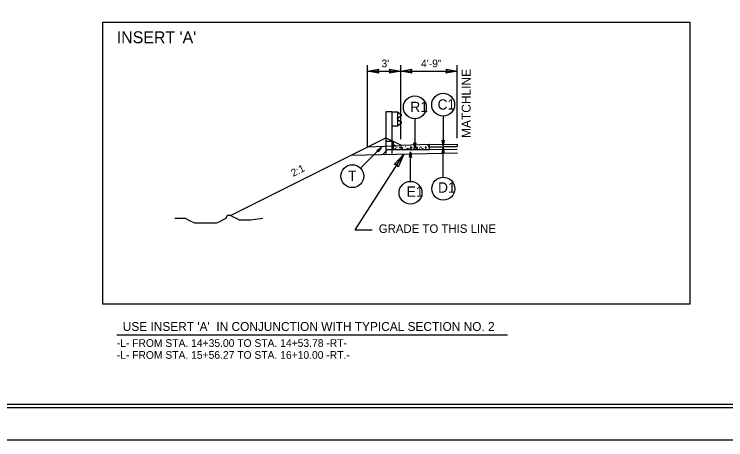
# Model space of a CAD drawing. Extents: x 573771 to 574316, y -53454 to -53190.
# Drawn here: x 573963.4 to 574083, y -53453.5 to -53382.1 of the extents above; entities that cross this region are included whole.
import ezdxf

# ---------------------------------------------------------------- set-up
doc = ezdxf.new("R2010")
doc.units = 0
for name, color, linetype in [('Sheet Cutting Line CELL', 7, 'Continuous'), ('Sheet Plot Border Inside CELL', 7, 'Continuous'), ('Sheet Plot Border Outside CELL', 7, 'Continuous'), ('Sheet Typical CELL', 7, 'Continuous'), ('Typical Curb CELL', 7, 'Continuous'), ('Typical Detail Wedge2 CELL', 7, 'Continuous'), ('Typical Guardrail CELL', 7, 'Continuous'), ('Typical ID Circle CELL', 7, 'Continuous'), ('Typical Pavement Slope Information CELL', 7, 'Continuous'), ('Typical Shoulder Slope CELL', 7, 'Continuous'), ('Typical Slope Point Local CELL', 7, 'Continuous'), ('Typical Terminator CELL', 7, 'Continuous'), ('Typical Text General CELL', 7, 'Continuous'), ('Typical Text Grade Point CELL', 7, 'Continuous'), ('Typical Text ID Circle CELL', 7, 'Continuous'), ('Typical Text Label CELL', 7, 'Continuous')]:
    doc.layers.add(name, color=color, linetype=linetype)

msp = doc.modelspace()

# ---------------------------------------------------------------- linework, layer by layer
at = {"layer": 'Sheet Cutting Line CELL'}
msp.add_line((573911.95, -53453.54), (574316.11, -53453.54), dxfattribs=at)
at = {"layer": 'Sheet Plot Border Inside CELL'}
msp.add_line((574033.2, -53404.41), (574037.88, -53404.31), dxfattribs=at)
msp.add_lwpolyline([(574315.03, -53194.93), (573915.07, -53194.93), (573915.07, -53448.15), (574315.03, -53448.15)], close=True, dxfattribs=at)
at = {"layer": 'Sheet Plot Border Outside CELL'}
msp.add_lwpolyline([(574316.11, -53189.54), (573911.95, -53189.54), (573911.95, -53453.54), (574316.11, -53453.54)], close=True, dxfattribs=at)
at = {"layer": 'Sheet Typical CELL'}
msp.add_lwpolyline([(574312.03, -53195.54), (573952.03, -53195.54), (573952.03, -53447.54), (574312.03, -53447.54)], close=True, dxfattribs=at)
at = {"layer": 'Typical Curb CELL'}
for p, q in [((574027.16, -53404.82), (574027.16, -53403.47)), ((574028.53, -53404.16), (574027.16, -53403.47)), ((574027.23, -53404.23), (574027.54, -53404.14)), ((574027.51, -53404.32), (574027.23, -53404.23)), ((574027.54, -53404.14), (574027.51, -53404.32)), ((574028.57, -53404.39), (574028.36, -53404.54)), ((574028.36, -53404.54), (574028.7, -53404.62)), ((574033.18, -53403.99), (574028.53, -53404.16)), ((574028.7, -53404.62), (574028.57, -53404.39)), ((574030.05, -53404.28), (574029.98, -53404.51)), ((574029.98, -53404.51), (574030.22, -53404.52)), ((574030.22, -53404.52), (574030.05, -53404.28)), ((574031.07, -53404.39), (574030.86, -53404.54)), ((574030.86, -53404.54), (574031.19, -53404.62)), ((574031.19, -53404.62), (574031.07, -53404.39)), ((574032.55, -53404.28), (574032.48, -53404.51)), ((574032.48, -53404.51), (574032.72, -53404.52)), ((574032.72, -53404.52), (574032.55, -53404.28)), ((574033.2, -53403.99), (574033.2, -53403.99)), ((574033.2, -53404.82), (574033.2, -53404.01)), ((574027.16, -53404.82), (574033.2, -53404.82))]:
    msp.add_line(p, q, dxfattribs=at)
for centre in [(574027.29, -53404.05), (574027.72, -53404.5), (574028.24, -53404.44), (574028.27, -53404.54), (574028.68, -53404.51), (574029.16, -53404.36), (574029.41, -53404.42), (574030.22, -53404.5), (574030.41, -53404.52), (574030.71, -53404.32), (574030.73, -53404.44), (574030.77, -53404.54), (574031.18, -53404.51), (574031.66, -53404.36), (574031.76, -53404.42), (574031.91, -53404.42), (574032.21, -53404.24), (574032.94, -53404.09), (574033.02, -53404.34), (574027.48, -53404.6), (574028.62, -53404.71), (574029.07, -53404.59), (574029.48, -53404.67), (574029.59, -53404.6), (574029.98, -53404.6), (574030.6, -53404.61), (574031.57, -53404.59), (574031.98, -53404.67), (574032.09, -53404.6)]:
    msp.add_circle(centre, 0.016, dxfattribs=at)
msp.add_arc((574033.18, -53404.01), 0.0208, 0, 92.048, dxfattribs=at)
at = {"layer": 'Typical Detail Wedge2 CELL'}
for p, q in [((573978.32, -53383.41), (574077.04, -53383.41)), ((573978.32, -53430.77), (573978.32, -53383.41)), ((574077.04, -53430.77), (574077.04, -53383.41)), ((574077.04, -53430.77), (573978.32, -53430.77))]:
    msp.add_line(p, q, dxfattribs=at)
at = {"layer": 'Typical Guardrail CELL'}
for p, q in [((574026.87, -53398.5), (574025.87, -53398.5)), ((574025.87, -53398.5), (574025.87, -53403.47)), ((574026.87, -53398.5), (574026.87, -53403.47)), ((574026.87, -53398.5), (574027.86, -53398.5)), ((574027.86, -53398.5), (574027.86, -53400.82)), ((574027.86, -53398.5), (574028.44, -53398.9)), ((574027.86, -53399.56), (574028.44, -53399.16)), ((574027.86, -53399.66), (574027.86, -53399.56)), ((574027.86, -53399.66), (574027.86, -53399.75)), ((574027.86, -53399.75), (574028.44, -53400.16)), ((574026.87, -53400.82), (574027.86, -53400.82)), ((574027.86, -53400.82), (574028.44, -53400.41)), ((574026.87, -53403.47), (574025.87, -53403.47)), ((574025.87, -53403.47), (574025.87, -53405.49)), ((574026.87, -53403.47), (574026.87, -53405.49))]:
    msp.add_line(p, q, dxfattribs=at)
for centre, start, end in [((574028.35, -53399.03), 304.9888, 54.997), ((574028.35, -53400.28), 304.9634, 54.9941)]:
    msp.add_arc(centre, 0.155, start, end, dxfattribs=at)
at = {"layer": 'Typical ID Circle CELL'}
for p, q in [((574030.75, -53399.63), (574030.75, -53404.6)), ((574035.51, -53399.21), (574035.51, -53404.18)), ((574021.6, -53407.92), (574025.12, -53404.41)), ((574035.53, -53409.46), (574035.53, -53404.49)), ((574030.02, -53410.15), (574030.02, -53405.18))]:
    msp.add_line(p, q, dxfattribs=at)
for centre in [(574030.75, -53397.71), (574035.51, -53397.29), (574020.24, -53409.28), (574030.02, -53412.07), (574035.53, -53411.39)]:
    msp.add_circle(centre, 1.92, dxfattribs=at)
at = {"layer": 'Typical Pavement Slope Information CELL'}
for p, q in [((574022.8, -53404.36), (574022.8, -53390.65)), ((574028.37, -53403.05), (574028.37, -53390.65)), ((574037.87, -53402.89), (574037.87, -53390.65)), ((574022.8, -53391.65), (574028.37, -53391.65)), ((574028.37, -53391.65), (574037.87, -53391.65)), ((574025.87, -53402.83), (574027.16, -53403.47)), ((574022.8, -53404.36), (574028.53, -53404.16)), ((574033.2, -53403.99), (574037.87, -53403.89)), ((574033.2, -53404.41), (574033.2, -53403.99)), ((574037.88, -53404.31), (574033.2, -53404.41)), ((574037.87, -53403.89), (574037.88, -53404.31)), ((574020, -53405.76), (574037.9, -53405.39)), ((574025.36, -53405.65), (574026.16, -53404.82)), ((574026.16, -53404.82), (574027.16, -53404.82)), ((574033.2, -53404.82), (574037.89, -53404.73))]:
    msp.add_line(p, q, dxfattribs=at)
at = {"layer": 'Typical Shoulder Slope CELL'}
msp.add_line((574033.2, -53403.99), (574037.87, -53403.89), dxfattribs=at)
at = {"layer": 'Typical Slope Point Local CELL'}
msp.add_line((573999.74, -53415.89), (574025.87, -53402.83), dxfattribs=at)
msp.add_lwpolyline([(574005.18, -53416.41), (574003.11, -53416.67), (574002.59, -53416.67), (574001.81, -53416.67), (574001.29, -53416.67), (574000.77, -53416.41), (574000.25, -53416.15), (573999.74, -53415.89), (573999.22, -53415.89), (573998.96, -53416.41), (573998.44, -53416.67), (573997.92, -53416.93), (573997.4, -53417.19), (573996.88, -53417.19), (573996.36, -53417.19), (573995.85, -53417.19), (573995.33, -53417.19), (573994.81, -53417.19), (573994.29, -53417.19), (573993.77, -53417.19), (573993.25, -53416.93), (573992.73, -53416.67), (573992.21, -53416.41), (573991.44, -53416.41), (573990.92, -53416.41), (573990.4, -53416.41)], dxfattribs=at)
at = {"layer": 'Typical Terminator CELL'}
for points in [[(574024.67, -53391.97), (574022.8, -53391.65), (574024.68, -53391.31), (574024.44, -53391.65)], [(574026.49, -53391.32), (574028.37, -53391.65), (574026.48, -53391.98), (574026.72, -53391.65)], [(574030.24, -53391.97), (574028.37, -53391.65), (574030.25, -53391.31), (574030.01, -53391.65)], [(574035.99, -53391.32), (574037.87, -53391.65), (574035.98, -53391.98), (574036.22, -53391.65)], [(574035.67, -53403.24), (574035.51, -53404.18), (574035.35, -53403.24), (574035.51, -53403.36)], [(574024.34, -53404.96), (574025.12, -53404.41), (574024.57, -53405.19), (574024.54, -53404.99)], [(574030.92, -53403.66), (574030.75, -53404.6), (574030.59, -53403.66), (574030.75, -53403.78)], [(574035.36, -53405.43), (574035.53, -53404.49), (574035.69, -53405.44), (574035.53, -53405.32)], [(574027.29, -53407.33), (574028.9, -53405.58), (574027.97, -53407.78), (574027.79, -53407.31)], [(574029.86, -53406.11), (574030.02, -53405.18), (574030.19, -53406.12), (574030.02, -53406)]]:
    msp.add_lwpolyline(points, close=True, dxfattribs=at)
at = {"layer": 'Typical Text Grade Point CELL'}
for q in [(574028.9, -53405.58), (574023.6, -53418.32)]:
    msp.add_line((574020.7, -53418.32), q, dxfattribs=at)
at = {"layer": 'Typical Text Label CELL'}
msp.add_line((573980.64, -53435.95), (574046.33, -53435.95), dxfattribs=at)

# ---------------------------------------------------------------- texts
at = {"layer": 'Typical Detail Wedge2 CELL'}
msp.add_text("INSERT 'A'", height=2, dxfattribs=at).set_placement((573980.65, -53386.96))
msp.add_text('MATCHLINE', height=1.5, rotation=90, dxfattribs=at).set_placement((574040.12, -53402.87))
at = {"layer": 'Typical Pavement Slope Information CELL'}
for s, height, p in [("3'", 1.295, (574025.14, -53391)), ('4\'-9"', 1.295, (574031.79, -53391)), ('-L- FROM STA. 14+35.00 TO STA. 14+53.78 -RT- ', 1.2952, (573980.64, -53437.95)), ('-L- FROM STA. 15+56.27 TO STA. 16+10.00 -RT.- ', 1.2952, (573980.64, -53439.95))]:
    msp.add_text(s, height=height, dxfattribs=at).set_placement(p)
at = {"layer": 'Typical Slope Point Local CELL'}
msp.add_text('2:1', height=1.25, rotation=26.5659, dxfattribs=at).set_placement((574010.31, -53409.41))
at = {"layer": 'Typical Text General CELL'}
msp.add_text('GRADE TO THIS LINE', height=1.4323, dxfattribs=at).set_placement((574024.69, -53418.81))
at = {"layer": 'Typical Text ID Circle CELL'}
for s, p in [('R1', (574029.99, -53398.52)), ('C1', (574034.57, -53398.1)), ('T ', (574019.53, -53410.07)), ('D1', (574034.65, -53412.05)), ('E1', (574029.38, -53412.73))]:
    msp.add_text(s, height=1.722, dxfattribs=at).set_placement(p)
at = {"layer": 'Typical Text Label CELL'}
msp.add_text("USE INSERT 'A'  IN CONJUNCTION WITH TYPICAL SECTION NO. 2", height=1.4919, dxfattribs=at).set_placement((573981.66, -53435.27))

doc.saveas('drawing.dxf')
